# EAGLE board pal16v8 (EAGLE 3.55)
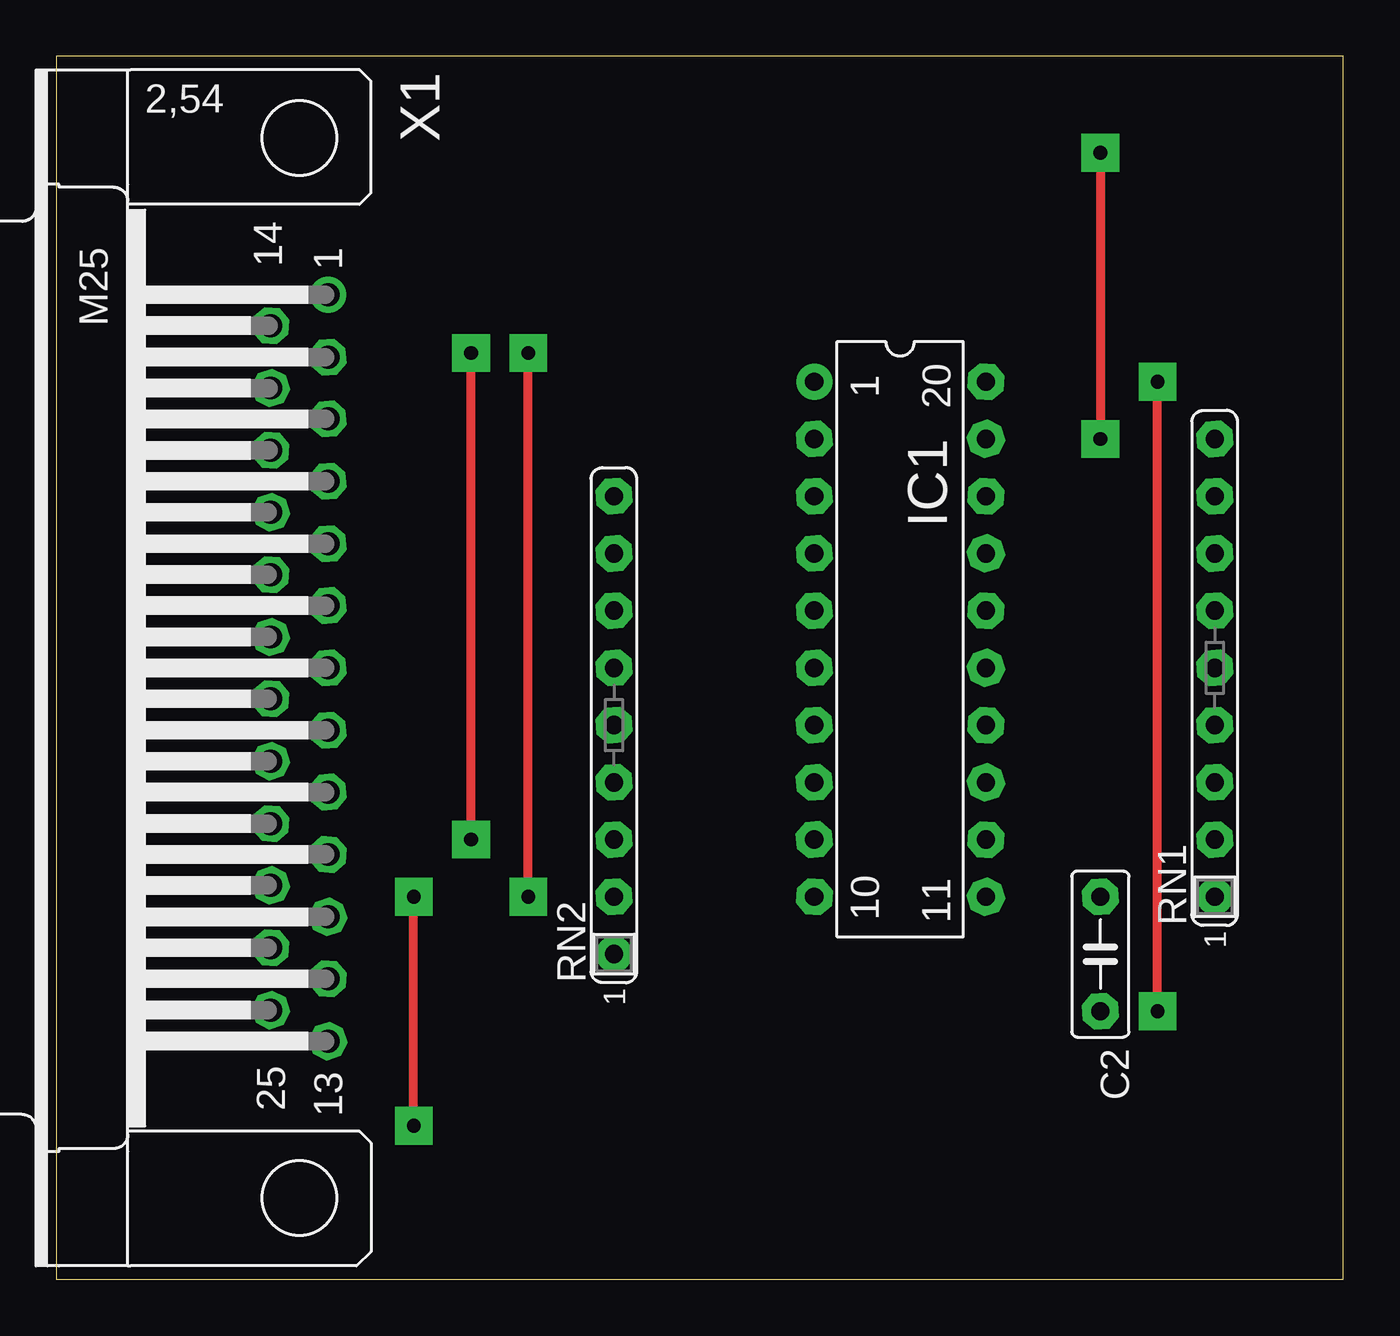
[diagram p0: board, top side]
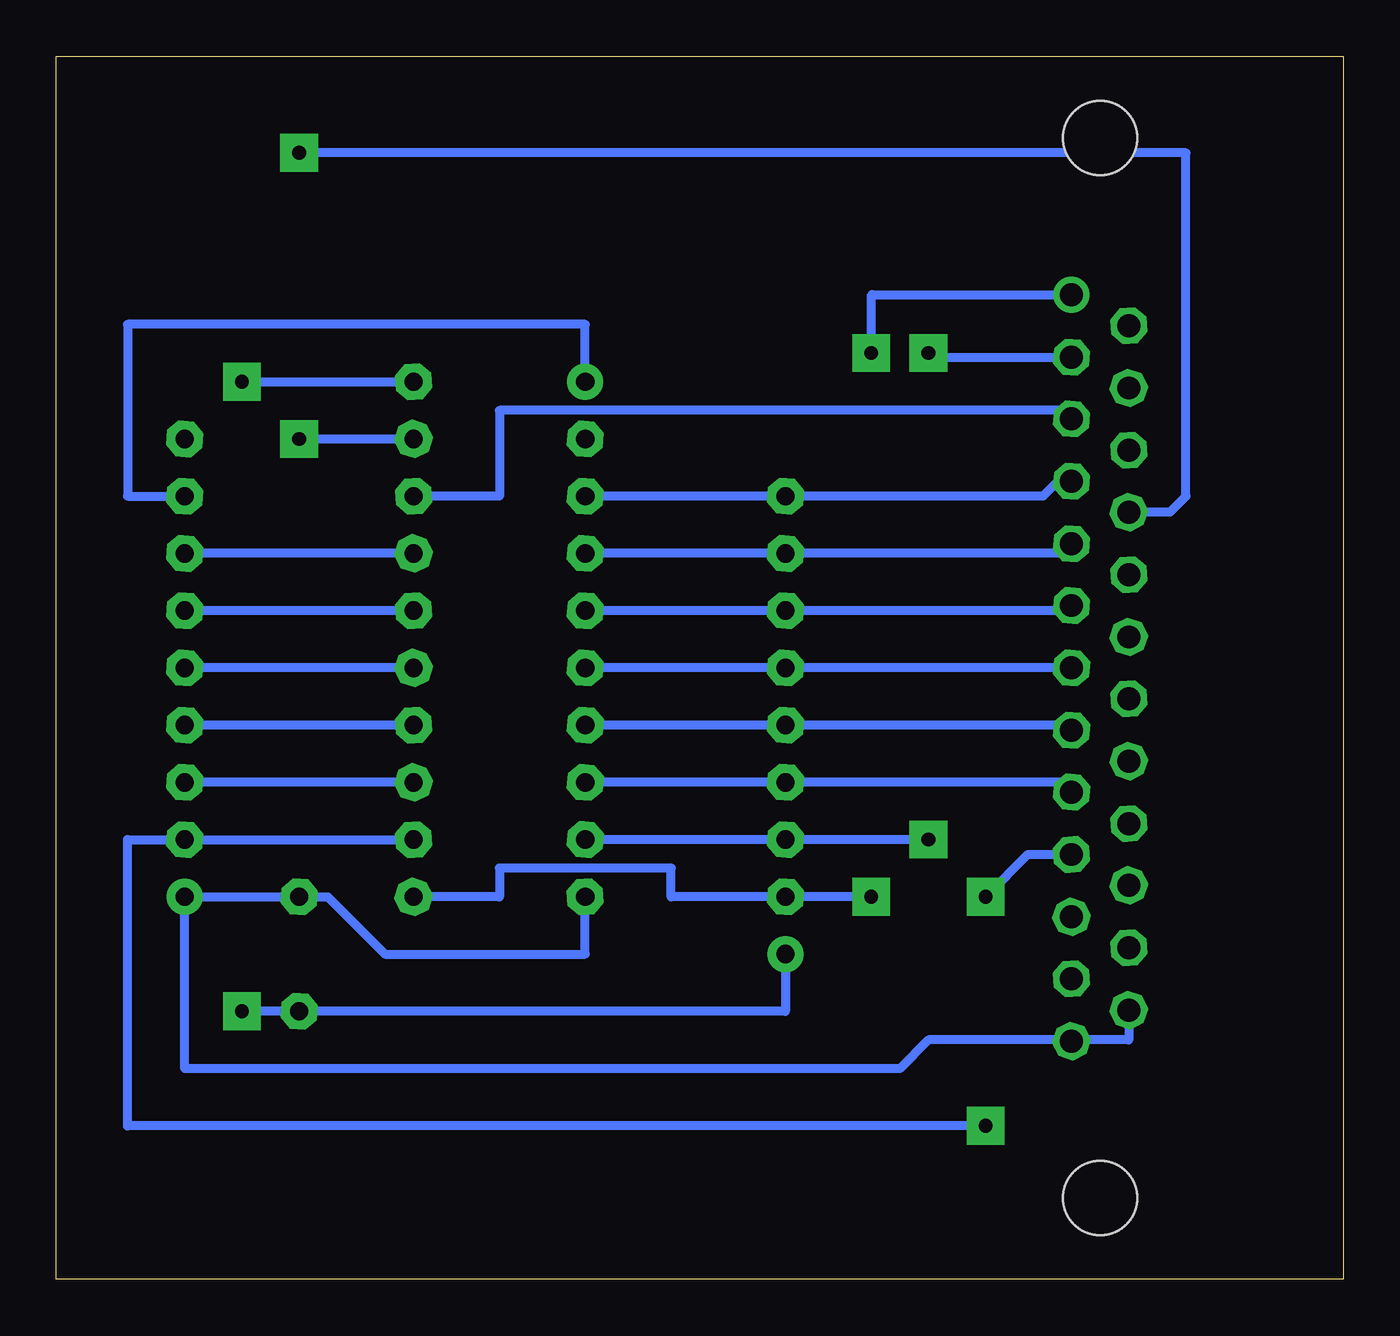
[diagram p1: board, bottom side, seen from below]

Size 57.13 x 54.28 mm. Coordinates in mm from the lower left corner, seen from the top.
Outline: 0,0 57.13,0 57.13,54.28 0,54.28 0,0
Copper layers used: Top, Bottom

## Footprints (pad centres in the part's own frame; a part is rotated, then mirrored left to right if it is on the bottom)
B2,5 = drill 0.813 pad 1.6 octagon:  -2.54,0;  2.54,0
L20 = drill 0.813 pad 1.6 round:  -11.43,-3.81 | drill 0.813 pad 1.6 octagon:  -8.89,-3.81;  -6.35,-3.81;  -3.81,-3.81;  -1.27,-3.81;  1.27,-3.81;  3.81,-3.81;  6.35,-3.81;  8.89,-3.81;  11.43,-3.81;  11.43,3.81;  8.89,3.81;  6.35,3.81;  3.81,3.81;  1.27,3.81;  -1.27,3.81;  -3.81,3.81;  -6.35,3.81;  -8.89,3.81;  -11.43,3.81
04/5 = drill 0.813 pad 1.6 octagon:  -2.54,0;  2.54,0
L9 = drill 0.813 pad 1.6 round:  -10.16,0 | drill 0.813 pad 1.6 octagon:  -7.62,0;  -5.08,0;  -2.54,0;  0,0;  2.54,0;  5.08,0;  7.62,0;  10.16,0
5H = drill 1.016 pad 1.6 octagon:  16.561,1.27;  13.792,1.27;  11.049,1.27;  8.28,1.27;  5.512,1.27;  2.769,1.27;  0,1.27;  -2.769,1.27;  -5.512,1.27;  -8.28,1.27;  -11.049,1.27;  -13.792,1.27;  15.189,-1.27;  12.421,-1.27;  9.652,-1.27;  6.909,-1.27;  4.14,-1.27;  1.372,-1.27;  -1.372,-1.27;  -4.14,-1.27;  -6.909,-1.27;  -9.652,-1.27;  -12.421,-1.27;  -15.189,-1.27 | drill 1.016 pad 1.6 round:  -16.561,1.27 | hole 3.302: 23.52,0; -23.52,0

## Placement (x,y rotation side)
C2  C5B2,5  [B2,5]  46.35,14.44 270 top
IC1  16V8  [L20]  37.46,28.41 270 top
R1  0204/5  [04/5]  not placed on the board
R2  0204/5  [04/5]  not placed on the board
R3  0204/5  [04/5]  not placed on the board
R4  0204/5  [04/5]  not placed on the board
R5  0204/5  [04/5]  not placed on the board
R6  0204/5  [04/5]  not placed on the board
R7  0204/5  [04/5]  not placed on the board
R8  0204/5  [04/5]  not placed on the board
R9  0204/5  [04/5]  not placed on the board
R10  0204/5  [04/5]  not placed on the board
R11  0204/5  [04/5]  not placed on the board
RN1  G08R  [L9]  51.43,27.14 90 top
RN2  G08R  [L9]  24.76,24.6 90 top
RN3  G08R  [L9]  not placed on the board
X1  M25H  [5H]  10.79,27.14 270 top

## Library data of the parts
C2 = cap
IC1 = pal
R1-R11 = r
RN1-RN3 = r-sil
X1 = subd

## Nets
GND: C2. IC1. RN1. X1.
N$1: IC1. RN1. X1.
N$2: IC1. RN1.
N$3: IC1. RN1.
N$4: IC1. RN1.
N$5: IC1. RN1.
N$6: IC1. RN1.
N$7: IC1. RN1.
N$9: IC1. RN2. X1.
N$10: IC1. RN2. X1.
N$11: IC1. RN2. X1.
N$12: IC1. RN2. X1.
N$13: IC1. RN2. X1.
N$14: IC1. RN2. X1.
N$15: IC1. RN2. X1.
N$16: IC1. RN2. X1.
N$17: IC1. X1.
N$24: IC1. X1.
VCC: C2. IC1. RN2.

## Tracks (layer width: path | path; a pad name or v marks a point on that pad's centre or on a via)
GND
  Bottom 0.406: 33.65,16.98 33.65,14.44 42.54,14.44 45.08,16.98 46.35,16.98 51.43,16.98 51.43,9.36 19.68,9.36 18.41,10.63 9.52,10.63 9.52,11.95
N$1  (via drill 0.61 pad 1.68)
  Top 0.406: v15.87,6.82 v15.87,16.98
  Bottom 0.406: 51.43,19.52 41.27,19.52 51.43,19.52 | 51.43,19.52 53.97,19.52 53.97,6.82 v15.87,6.82 | 12.06,18.86 13.99,18.86 v15.87,16.98
N$2
  Bottom 0.406: 41.27,22.06 51.43,22.06
N$3
  Bottom 0.406: 41.27,24.6 51.43,24.6
N$4
  Bottom 0.406: 41.27,27.14 51.43,27.14
N$5
  Bottom 0.406: 41.27,29.68 51.43,29.68
N$6
  Bottom 0.406: 41.27,32.22 51.43,32.22
N$7
  Bottom 0.406: 33.65,39.84 33.65,42.38 53.97,42.38 53.97,34.76 51.43,34.76
N$8  (via drill 0.61 pad 1.68)
  other vias: 48.89,39.84
N$9
  Bottom 0.406: RN2. 33.65,34.76 RN2. | 12.06,35.42 12.67,35.42 13.33,34.76 RN2.
N$10
  Bottom 0.406: 33.65,32.22 24.76,32.22 12.06,32.22 12.06,32.65
N$11
  Bottom 0.406: 33.65,29.68 24.76,29.68 12.06,29.68 12.06,29.91
N$12
  Bottom 0.406: 33.65,27.14 24.76,27.14 12.06,27.14
N$13
  Bottom 0.406: 33.65,24.6 24.76,24.6 12.06,24.6 12.06,24.37
N$14
  Bottom 0.406: 33.65,22.06 24.76,22.06 12.06,22.06 12.06,21.63
N$15  (via drill 0.61 pad 1.68)
  Top 0.406: v18.41,19.52 v18.41,41.11
  Bottom 0.406: 33.65,19.52 24.76,19.52 v18.41,19.52 | 12.06,40.93 18.23,40.93 v18.41,41.11
N$16  (via drill 0.61 pad 1.68)
  Top 0.406: v20.95,16.98 v20.95,41.11
  Bottom 0.406: 41.27,16.98 37.46,16.98 37.46,18.25 29.84,18.25 29.84,16.98 24.76,16.98 v20.95,16.98 | 12.06,43.7 20.9,43.7 20.95,43.65 v20.95,41.11
N$17
  Bottom 0.406: 41.27,34.76 37.46,34.76 37.46,38.57 12.06,38.57 12.06,38.19
N$18  (via drill 0.61 pad 1.68)
  other vias: 48.89,11.9
N$19  (via drill 0.61 pad 1.68)
  other vias: 20.95,16.98
N$20  (via drill 0.61 pad 1.68)
  other vias: 18.41,19.52
N$21  (via drill 0.61 pad 1.68)
  other vias: 18.41,41.11
N$22  (via drill 0.61 pad 1.68)
  other vias: 20.95,41.11
N$23  (via drill 0.61 pad 1.68)
  other vias: 46.35,37.3
N$24  (via drill 0.61 pad 1.68)
  Top 0.406: v46.35,50 v46.35,37.3
  Bottom 0.406: v46.35,37.3 41.27,37.3 | 9.52,34.05 7.69,34.05 6.98,34.76 6.98,50 v46.35,50
N$25  (via drill 0.61 pad 1.68)
  other vias: 46.35,50
N$26  (via drill 0.61 pad 1.68)
  other vias: 15.87,16.98
VCC  (via drill 0.61 pad 1.68)
  Top 0.406: v48.89,11.9 v48.89,39.84
  Bottom 0.406: 24.76,14.44 24.76,11.9 C2. v48.89,11.9 | v48.89,39.84 IC1.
